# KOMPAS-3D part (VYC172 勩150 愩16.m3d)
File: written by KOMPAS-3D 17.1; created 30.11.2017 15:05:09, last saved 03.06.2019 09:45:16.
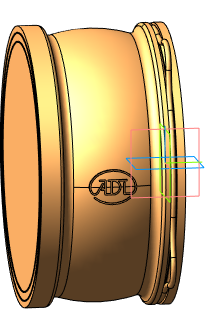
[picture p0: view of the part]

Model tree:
1. Операция без истории:2  (labels: Сталь 20  ГОСТ 1050-2013)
